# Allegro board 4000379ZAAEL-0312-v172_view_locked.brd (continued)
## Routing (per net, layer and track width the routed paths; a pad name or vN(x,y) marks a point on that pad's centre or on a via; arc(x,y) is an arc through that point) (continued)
PGND: length 56.5
  TOP w0.305: U909.23 v2(35.22,137.1) ; U909.18 v2(38.47,137.1) ; U909.11 38.47,134.04 v2(38.48,134.05) ; v2(35.88,134.05) 35.87,134.04 U909.7 ; U909.22 35.87,137.23 v2(36,137.1)
  TOP w0.381: 35.43,122.03 PU30.12 ; PU30.12 35.43,123 ; PU30.12 34.95,122.52 ; PU30.12 35.92,122.52 ; PU30.15 34.72,124.12 ; PU30.15 34.23,123.63 ; PU30.15 34.23,124.6 ; PU30.15 33.75,124.12 ; 36.15,122.52 PU30.10 ; PU30.10 37.12,122.52 ; PU30.10 36.63,122.03 ; PU30.10 36.63,123 ; 36.15,124.12 PU30.11 ; PU30.11 36.63,124.6 ; PU30.11 37.12,124.12 ; PU30.11 36.63,123.63 ; PU30.14 34.72,122.52 ; PU30.14 34.23,123 ; PU30.14 34.23,122.03 ; PU30.14 33.75,122.52 ; PU30.13 35.92,124.12 ; PU30.13 34.95,124.12 ; PU30.13 35.43,124.6 ; PU30.13 35.43,123.63
  TOP w0.508: U22.5 v2(22.61,135.38) ; C720.1 v2(26.42,133.48)
  L2 w0.381: 33.75,124.12 PU30.15 ; PU30.15 34.23,124.6 ; PU30.15 34.23,123.63 ; PU30.15 34.72,124.12 ; PU30.12 35.92,122.52 ; PU30.12 34.95,122.52 ; PU30.12 35.43,122.03 ; PU30.12 35.43,123 ; 36.15,122.52 PU30.10 ; PU30.10 37.12,122.52 ; PU30.10 36.63,123 ; PU30.10 36.63,122.03 ; PU30.13 35.92,124.12 ; PU30.13 35.43,124.6 ; PU30.13 34.95,124.12 ; PU30.13 35.43,123.63 ; PU30.11 36.63,124.6 ; PU30.11 37.12,124.12 ; PU30.11 36.63,123.63 ; PU30.11 36.15,124.12 ; PU30.14 34.23,123 ; PU30.14 34.72,122.52 ; PU30.14 33.75,122.52 ; PU30.14 34.23,122.03
  L3 w0.381: 36.63,123.63 PU30.11 ; PU30.11 36.15,124.12 ; PU30.11 37.12,124.12 ; PU30.11 36.63,124.6 ; PU30.10 36.63,123 ; PU30.10 37.12,122.52 ; PU30.10 36.63,122.03 ; PU30.10 36.15,122.52 ; PU30.12 35.92,122.52 ; PU30.12 35.43,123 ; PU30.12 35.43,122.03 ; PU30.12 34.95,122.52 ; PU30.15 34.23,124.6 ; PU30.15 33.75,124.12 ; PU30.15 34.72,124.12 ; PU30.15 34.23,123.63 ; PU30.13 35.92,124.12 ; PU30.13 35.43,123.63 ; PU30.13 35.43,124.6 ; PU30.13 34.95,124.12 ; 34.23,122.03 PU30.14 ; PU30.14 33.75,122.52 ; PU30.14 34.23,123 ; PU30.14 34.72,122.52
  BOTTOM w0.381: PU30.10 36.63,123 ; PU30.10 37.12,122.52 ; PU30.10 36.15,122.52 ; PU30.10 36.63,122.03 ; PU30.12 35.43,123 ; PU30.12 35.92,122.52 ; PU30.12 35.43,122.03 ; PU30.12 34.95,122.52 ; PU30.13 35.43,124.6 ; PU30.13 34.95,124.12 ; PU30.13 35.43,123.63 ; PU30.13 35.92,124.12 ; 36.63,123.63 PU30.11 ; PU30.11 37.12,124.12 ; PU30.11 36.15,124.12 ; PU30.11 36.63,124.6 ; PU30.14 34.23,123 ; PU30.14 33.75,122.52 ; PU30.14 34.72,122.52 ; PU30.14 34.23,122.03 ; PU30.15 34.72,124.12 ; PU30.15 34.23,124.6 ; PU30.15 33.75,124.12 ; PU30.15 34.23,123.63
  BOTTOM w0.508: C8572.1 v2(32.64,136.64)
  BOTTOM w0.762: v2(30.43,136.72) C8573.2
  vias: v2(6.35,105.03) v2(6.73,135.25) v2(6.73,131.32) v2(6.73,127.38) v2(6.73,123.06) v2(6.86,118.62) v2(7.75,114.55) v2(7.87,107.82) v2(8.89,137.79) v2(9.14,109.35) v2(9.14,108.58) v2(9.27,122.56) v2(9.53,133.22) v2(9.53,128.14) v2(9.65,116.46) v2(10.03,112.14) v2(10.03,110.62) v2(10.16,109.35) v2(10.16,108.58) v2(11.94,119.13) v2(12.06,137.79) v2(12.32,125.48) v2(13.02,109.35) v2(13.08,108.52) v2(13.84,136.14) v2(13.84,135.13) v2(13.97,109.35) v2(13.97,108.52) v2(14.35,122.43) v2(14.61,137.79) v2(15.11,136.21) v2(15.11,135.19) v2(16.51,136.21) v2(16.51,135.19) v2(16.89,125.35) v2(17.78,137.79) v2(17.97,136.21) v2(17.97,135.19) v2(19.68,122.56) v2(20.95,137.79) v2(22.35,119.89) v2(22.48,125.22) v2(22.61,131.44) v2(24.51,137.79) v2(25.02,117.35) v2(25.15,122.3) v2(25.4,128.4) v2(26.8,115.32) v2(28.07,137.79) v2(29.78,130.94) v2(30.48,134.3) v2(30.73,125.92) v2(30.8,138.75) v2(30.8,126.87) v2(31.05,115.57) v2(31.05,114.36) v2(31.69,126.87) v2(31.69,125.92) v2(31.69,124.97) v2(31.88,143.76) v2(32.26,115.57) v2(32.26,114.36) v2(32.64,126.87) v2(32.64,125.92) v2(32.64,124.97) v2(32.77,95) v2(32.77,91.19) v2(33.02,144.72) v2(33.15,107.7) v2(33.53,130.05) v2(33.46,115.57) v2(33.46,114.43) v2(34.04,99.82) v2(34.23,109.66) v2(34.23,108.65) v2(34.16,98.3) v2(34.92,130.05) v2(35.56,102.74) v2(36.07,129.29) v2(36.13,119.13) v2(36.2,117.47) v2(36.96,91.5) v2(37.59,101.35) v2(37.72,124.33) v2(37.72,122.87) v2(37.72,115.63) v2(37.72,114.49) v2(37.72,99.82) v2(37.72,98.42) v2(37.85,92.71) v2(38.93,144.78) v2(39.12,92.71) v2(39.37,140.46) v2(40.7,98.42) v2(40.7,96.84) v2(40.7,95.12) v2(40.7,93.54) v2(41.53,102.62) v2(41.66,140.46) v2(42.04,98.36) v2(42.04,96.77) v2(42.04,95.06) v2(42.04,93.47) v2(43.24,145.61) v2(43.24,144.78) v2(43.18,98.3) v2(43.18,96.71) v2(43.18,95) v2(43.18,93.41) v2(43.88,114.87) v2(44.01,125.03) v2(44.01,124.08) v2(44.01,123.06) v2(45.34,124.97) v2(46.61,124.97) v2(46.86,146.81) v2(46.86,145.03) v2(48.01,124.97) v2(49.09,114.94) v2(49.34,131.89) v2(49.34,124.21) v2(49.28,122.87) v2(49.4,135.89) v2(50.42,102.36) v2(51.05,139.7) v2(51.18,135.83) v2(51.18,131.89) v2(51.24,91.44) v2(51.56,145.8) v2(52.96,96.9) v2(53.09,117.41) v2(53.21,131.95) v2(55.12,107.95) v2(55.63,91.69) v2(55.69,123.63) v2(55.88,135.89) v2(57.09,122.24) v2(57.15,112.39) v2(57.28,103) v2(57.28,95.76)
SVDD0_CK: length 4.4
  TOP w0.203: v1(79.1,91.24) 79.1,91.27 79,91.36 E1U1.50
  BOTTOM w0.305: E1C97.1 79.62,91.24
  BOTTOM w0.508: v1(79.1,91.24) E1C98.1 81.53,91.24 E1C99.2 E1L5.2
SVDD0_TRX: length 0.8
  TOP w0.203: v1(77.5,91.19) 77.4,91.29 E1U1.46
VCC_0V6_DDR: length 29.3
  BOTTOM w0.203: R121.1 122.4,20.16 124.12,20.16 ; R123.1 122.39,25.52 124.12,25.52 ; 124.12,22.38 124.06,22.33 122.37,22.33 R128.1 ; R130.1 124.19,23.36 ; R125.1 124.12,24.48 122.38,24.48 R106.1
  BOTTOM w0.254: R119.1 116.89,30.94 116.89,33.23 117.42,33.23 R112.1 ; 124.73,21.24 122.25,21.24 R118.1 ; R107.1 120.3,28.2 122.29,28.2 R110.1 ; R113.1 120.43,29.28 122.29,29.28 R111.1 ; R109.1 124.12,25.52 ; 122.27,26.49 122.27,26.98 120.75,26.98 R105.1 ; R120.1 119.17,30.95 119.17,32.68 R116.1 118.49,32.8 118.02,32.8 118.02,30.86 R114.1
  vias: v2(127.76,23.55) v2(128.07,24.26) v2(128.07,22.83) v2(128.47,23.55)
VCC_0V9_PRX321: length 12.6
  TOP w0.127: R916.1 v2(125.96,60.79) 125.98,60.77
  TOP w0.203: U1.U14 v1(104.94,51.41) ; U1.P14 105.26,49.44 104.84,49.02
  TOP w0.254: U1.W22 102.04,51.88 v1(102.39,52.22) 102.73,51.88 U1.W20 ; U1.P18 v1(103.28,49.81) ; U1.W12 U1.U14 ; U1.T20 U1.T22 ; U1.P14 U1.T12
  TOP w0.305: v1(104.83,49.02) 104.88,49.02 U1.M14 ; 105.28,49.43 U1.P14 ; U1.T20 v1(103.19,50.6) 103.19,50.71 U1.U20 ; U1.P16 104.46,49.43 v1(104.07,49.04) 103.65,48.62 U1.M18 ; U1.U18 103.65,51.03 v1(104.01,50.67)
  BOTTOM w0.305: v1(102.39,52.22) 102.01,51.84 C209.1 C225.2 102.36,50.69 C215.1
  vias: v2(124.97,60.83) v2(124.97,59.94) v2(125.98,59.94)
VCC_0V9_PRX321_XFI: length 14
  TOP w0.203: U1.W10 106.89,51.88 v1(106.57,51.55) ; v1(100.86,53.01) 100.81,53.06 100.81,53.75 101.02,53.95 103.2,53.95 v1(103.3,53.85)
  TOP w0.254: U1.AC18 103.65,53.5 v1(103.3,53.85) ; v1(106.55,50.6) U1.T10 ; v1(100.86,53.01) 101.18,52.69 U1.AA24
  BOTTOM w0.305: v1(106.57,51.55) 106.32,51.31 106.04,51.31 C206.1 ; C189.1 98.91,53.08 C202.1 100.79,53.08 v1(100.86,53.01) ; v1(103.3,53.85) 103.75,53.4 104.52,53.4 105,52.93 105.35,52.93 C198.1 105.52,52.8 105.97,52.34 C206.1 ; C206.1 C2.1 105.98,50.6 v1(106.55,50.6)
VCC_1V0_8261BE: length 22.5
  TOP w0.203: E1U1.53 81.3,93.09 E1C58.2 ; v1(75.95,91.04) 75.8,91.18 E1U1.42 ; E1U1.32 71.51,93.49 70.99,92.97 70.99,91.69 E1C54.2 ; v1(80.9,94.8) 80.79,94.69 E1U1.57 ; 70.92,95.34 71.09,95.34 71.63,95.89 E1U1.26
  TOP w0.305: E1C54.2 70.11,91.62 E1C50.2 ; E1C51.2 70.92,96.1 E1C55.2 ; E1C37.2 82.02,93.01 E1C58.2 ; E1C56.2 v1(80.9,94.8)
  TOP w0.381: E1C50.2 E1C38.2 68.77,91.55 68.39,91.17 v1(68.39,90.81)
  TOP w0.508: v1(68.52,95.95) 68.52,96.44 E1C33.1 69.09,96.25 E1C30.1 70.77,96.25 E1C51.2 ; v1(83.92,92.92) E1C35.1 83.16,92.89 E1C37.2
  BOTTOM w0.305: E1C53.2 75.97,91.01 v1(75.95,91.04)
  BOTTOM w0.508: E1C36.1 81.56,95.99 E1C52.2 81.33,94.8 v1(80.9,94.8) ; E1C79.2 85.42,94.09 85.42,93.43 84.92,92.92 v1(83.92,92.92)
  vias: v1(68.26,89.41) v1(68.26,88.77) v1(68.26,88.07) v1(68.26,87.44) v1(68.83,89.41) v1(68.83,88.77) v1(68.83,88.07) v1(68.83,87.44) v1(71.12,102.43) v1(71.12,101.79) v1(71.75,102.43) v1(71.75,101.79) v1(74.61,87.94) v1(74.61,87.31) v1(83.24,89.03) v1(83.24,88.4) v1(83.85,89.01) v1(83.85,88.4)
VCC_1V8_PRX321: length 147.2
  TOP w0.254: v4(86.74,44.67) 87.15,44.67 91.13,48.65 91.13,48.84 R172.1
  TOP w0.305: C1004.1 120.21,60.91
  TOP w0.508: v4(86.74,44.67) v4(86.06,45.35) 86.06,45.36 C21.1 83.63,47.79 83.63,49.48 ; v4(104.39,60.77) 105.03,60.13 v1(105.03,58.01) ; v2(126.36,48.01) C1005.1 C1006.1 R984.1 128.3,48.75 PU902.5 ; 83.63,49.48 C16.1 ; 83.63,49.48 v4(83.63,51.51) ; PR113.1 143.87,34.39 v2(143.75,34.28) ; v2(120.21,56.07) v2(120.21,61.9) ; C18.1 v2(94.74,60.83)
  L3 w0.508: v2(143.75,34.28) 131.64,34.28 130.19,35.73 130.19,42.95 126.36,46.77 v2(126.36,48.01) ; v2(120.21,61.9) 120.02,61.72 111.56,61.72 109.98,60.13 105.03,60.13 v4(104.39,60.77) 104.33,60.83 v2(94.74,60.83) 94.17,60.26 92.38,60.26 v4(83.63,51.51)
  BOTTOM w0.127: 126.03,49.5 C926.1 ; C27.1 94.95,44.67 ; 119.23,55.85 C927.1 ; C26.1 93.45,44.67 ; C25.1 94.16,44.67 ; 117.35,51.89 C922.1
  BOTTOM w0.305: C22.1 124.65,51.94
  BOTTOM w0.508: 97.05,44.67 R928.1 ; 97.05,44.67 98.53,44.67 99.38,43.81 FB13.1 ; 97.05,44.67 v4(86.74,44.67) v4(86.06,45.35) ; FB10.1 104.33,57.5 104.84,58.01 v1(105.03,58.01) ; C23.1 114.28,54.42 114.28,54.48 113.78,54.99 112.72,54.99 FB15.1 ; C23.1 117.73,54.36 ; C23.1 FB6.1 ; 117.73,54.36 117.73,52.27 116.89,51.44 115.71,51.44 ; 117.73,54.36 119.44,56.07 v2(120.21,56.07) 123.51,56.07 124.65,54.93 124.65,50.89 126.36,49.17 v2(126.36,48.01) ; 115.71,51.44 115.71,51.83 115.87,51.99 FB5.1 ; 115.71,51.44 FB12.1
VCC_1V8_PRX321_PLL: length 24.6
  TOP w0.508: v2(125.86,53.09) 125.89,53.05 C1009.1 C1010.1 128.07,53.04 PU908.5
  BOTTOM w0.305: 114.87,57.08 C1012.1
  BOTTOM w0.508: FB14.1 108.81,56.48 109.39,57.07 R980.1 111,57.07 C20.1 C19.1 111.96,57.08 124.34,57.08 125.86,55.56 v2(125.86,53.09)
VCC_1V9_8261BE: length 15.7
  TOP w0.127: R939.1 85.03,77.83 85.15,77.96 85.9,77.96 v2(85.92,77.98)
  TOP w0.203: v1(71.5,92.39) 71.44,92.46 71.44,92.75 71.77,93.09 E1U1.33 ; E1U1.24 71.58,96.69 v1(71.5,96.77) ; E1U1.55 v1(79.35,93.89) ; E1U1.36 73.4,90.95 73.4,90.94 E1C74.2
  TOP w0.305: E1R25.1 E1R24.1 72.82,89.49 v1(72.86,89.44) 73.09,89.44 73.4,89.74 E1C75.2 E1C74.2
  TOP w0.381: E1R3.1 68.52,99.39 v1(68.52,98.81)
  BOTTOM w0.381: v1(68.52,98.81) 70.36,98.81 71.5,97.66 v1(71.5,96.77)
  BOTTOM w0.508: v1(79.35,93.89) 79.37,93.91 E1C69.2 80.11,93.88 E1C72.1
  vias: v1(82.17,103) v1(82.17,102.11) v1(82.93,103) v1(82.93,102.11) v2(85.92,79.95) v2(85.92,78.93) v2(86.93,79.95) v2(86.93,78.93) v2(86.93,78.04) v2(87.88,80.01) v2(87.88,78.93) v2(87.88,78.04) v2(91.57,103.25) v2(91.57,102.62) v2(91.57,101.85) v2(92.2,103.25) v2(92.2,102.62) v2(92.2,101.85) v2(92.84,103.25) v2(92.84,102.62) v2(92.84,101.85)
VCC_1V35_DDR: length 67.5
  TOP w0.152: v1(95.25,20.27) 95.35,20.37 96,20.37 96.41,20.78 96.57,20.79 U13.H2
  TOP w0.178: 96.56,17.59 96.37,17.59 95.96,17.18 95.29,17.18 v1(95.2,17.16) ; 96.56,17.59 U13.D2 ; 96.56,17.59 96.57,17.59
  TOP w0.203: U1.H25 100.27,47.13 100.27,47.39 100.01,47.65 100.01,47.96 100.28,48.23 100.79,48.23 v1(100.83,48.2) ; v1(107.31,47.41) U1.K8 107.75,47.84 107.75,48.59 U1.M8 ; U12.G7 112.94,19.99 113.04,19.89 113.36,19.89 113.87,19.38 v1(113.87,19.15) ; 117.74,15.19 U12.A1 ; 117.74,15.19 117.74,15.19 ; 117.74,15.19 117.74,15.38 117.13,15.99 116.94,15.99 U12.B2 ; 102.03,47.02 U1.H22
  TOP w0.254: U1.K24 101.21,47.81 v1(100.83,48.2) ; U13.A1 97.37,15.19 v1(97.77,14.79) ; U12.H2 116.94,20.79 v1(116.54,20.39) ; 90.96,24.79 90.97,24.79 ; 90.96,24.79 U13.N9 ; 90.96,24.79 89.71,24.79 89.41,25.12 v1(89.36,25.12) ; 111.33,26.39 111.34,26.39 ; 111.33,26.39 U12.R9 ; 111.33,26.39 111.22,26.39 v1(110.81,26.79) ; U12.N9 111.34,24.79 110.98,25.14 v1(110.76,25.14) ; v4(110.19,21.23) 110.6,20.82 111.31,20.82 111.34,20.79 U12.H9 ; v1(96.97,22.79) 96.57,22.39 U13.K2 ; v1(100.83,48.2) 100.83,48.24 ; v1(100.83,48.2) 101.21,48.58 U1.M24 ; v1(118.36,15.29) 118.29,15.21 118.29,15.19 117.74,15.19 ; v1(111.76,22.76) 111.77,22.76 112.14,22.39 U12.K8 ; v1(106.5,47.35) 106.5,47.4 106.09,47.81 U1.K12 ; v1(118.25,19.24) 118.14,19.19 117.74,19.19 U12.F1 ; U12.R1 117.74,26.39 118.01,26.11 v1(118.24,26.11) ; v1(98.18,26.78) 97.79,26.39 97.37,26.39 U13.R1 ; v1(97.8,25.22) 97.37,24.79 U13.N1 ; v1(118.41,16.87) 118.34,16.79 117.74,16.79 U12.C1 ; U1.H10 v1(107.31,47.41) ; U12.C9 111.34,16.79 v1(110.94,17.19) ; v1(117.34,17.99) 116.94,17.59 U12.D2 ; v1(90.32,16.87) 90.4,16.79 90.96,16.79 ; 90.96,16.79 90.97,16.79 ; 90.96,16.79 U13.C9 ; U12.K2 116.94,22.39 v1(117.33,22.79) ; U12.N1 117.74,24.79 v1(118.15,25.2) ; 107.72,47.81 U1.K8 ; U13.H9 90.97,20.79 v1(91.37,20.39) ; U13.C1 97.37,16.79 v1(96.97,16.39) 96.57,15.99 U13.B2 ; v1(92.14,22.77) 91.77,22.39 U13.K8 ; U13.G7 92.57,19.99 v1(92.97,19.59) ; U12.D9 111.34,17.59 v1(110.94,17.99) 111.34,18.39 U12.E9 ; v1(98.11,19.25) 97.39,19.25 97.37,19.19 U13.F1 ; U13.A8 91.77,15.19 v1(91.37,15.59) ; U1.H12 106.11,47 v1(106.5,46.61) ; v1(90.48,26.93) 90.48,26.88 90.97,26.39 U13.R9 ; v1(108.08,46.61) 108.47,47 U1.H6 ; U13.D9 90.97,17.59 v1(90.57,17.99) 90.97,18.39 U13.E9 ; v1(104.04,47.37) 104.06,47.39 104.06,47.41 U1.K16
  TOP w0.305: 101.62,46.61 101.62,46.6 ; 101.62,46.6 v1(101.61,46.58) ; 101.62,46.6 U1.H22 U1.K20 U1.H20 102.42,46.58 v1(102.41,46.58) 102.44,46.61 ; v1(112.19,14.5) 112.14,14.5 112.14,15.19 U12.A8 ; C116.1 v1(133.18,14.34)
  TOP w0.508: C973.1 104.01,11.81 v2(104.04,11.84) ; v2(131.29,22.35) 131.29,21.56 R938.1 ; C232.1 126.52,13.87 v2(127.09,14.44)
  BOTTOM w0.127: v1(106.5,46.61) 106.5,46.53 106.84,46.19 107.66,46.19 v1(108.08,46.61)
  BOTTOM w0.203: C102.1 110.38,27.06 110.43,27.01 110.62,26.79 v1(110.81,26.79) ; C115.1 89.44,27.77 90.27,26.93 v1(90.48,26.93)
  BOTTOM w0.254: C99.1 118.06,19.05 v1(118.25,19.24) ; C958.1 118.92,16.87 v1(118.41,16.87) ; 91.37,20.38 v1(91.37,20.39) ; v1(110.94,17.99) 111.19,18.24 111.19,18.49 C105.1 ; C104.1 118.65,25.19 118.17,25.19 v1(118.15,25.2) ; v1(91.37,15.59) 91.37,15.21 C961.1 ; C94.1 118.39,15.27 v1(118.36,15.29) ; v1(118.24,26.11) 118.36,25.99 C103.1 ; v1(112.19,14.5) 112.16,14.53 111.95,14.53 C960.1 ; v1(104.04,47.37) 103.57,47.37 C201.1 ; v1(110.94,17.19) 110.81,17.06 C95.1
  BOTTOM w0.305: v1(95.26,47.37) 95.26,46.96 C100.1 ; v4(110.19,21.23) 110.12,21.3 C96.1 ; C169.1 C168.1 100.82,48.2 v1(100.83,48.2) ; C142.1 117.31,18.01 v1(117.34,17.99) ; 102.41,46.57 v1(102.41,46.58) 102.06,46.24 C177.1 C191.1 ; v1(97.77,14.79) 97.89,14.91 C200.1 ; v1(90.57,17.99) 90.94,17.62 C112.1 ; v1(90.32,16.87) 90.37,16.81 C110.1 ; C113.1 97.83,25.25 v1(97.8,25.22) ; v1(95.25,20.27) 95.28,20.24 C959.1 ; C172.1 101.39,45.9 101.36,45.92 ; C195.1 98.21,19.15 v1(98.11,19.25) ; C140.1 92.74,19.28 92.97,19.51 v1(92.97,19.59) ; C159.1 98.25,26.71 v1(98.18,26.78) ; 101.36,45.92 C184.1 ; 101.36,45.92 101.36,46.34 v1(101.61,46.58) ; v1(91.37,20.39) 91.36,20.38 C106.1 ; C114.1 v1(111.58,38.84) ; C141.1 95.66,17.16 v1(95.2,17.16) ; v1(96.97,16.39) 97.14,16.56 C205.1
  BOTTOM w0.381: 102.41,46.58 v1(102.41,46.58)
  BOTTOM w0.457: C974.1 113.87,18.31 v1(113.87,19.15)
  BOTTOM w0.508: C971.1 102.22,19.6 v1(102.21,19.61) ; C972.1 94.25,17.31 v1(93.95,17.6)
  vias: v2(132.52,29.78) v2(132.52,28.77) v2(133.03,29.21) v2(133.79,29.21) v2(134.24,29.72) v2(134.24,28.64) v2(134.68,29.21)
VCC_3V3_8261BE: length 63.7
  TOP w0.203: 70.55,98.95 70.55,98.81 71.86,97.49 E1U1.22 ; E1U1.31 71.41,93.89 70.49,92.96 E1C91.1
  TOP w0.381: v1(69.47,92.2) 69.72,92.2 70.34,92.82 E1C91.1
  TOP w0.508: v2(85.28,86.04) 86.17,86.93 86.17,92.67 ER331.1 ; v1(69.18,98.2) 69.18,98.66 E1C88.1 70.42,99.08 70.55,98.95 E1C89.2 ; v2(67.37,91.69) 67.82,91.69 68.33,92.2 v1(69.47,92.2)
  TOP w1.016: RP1132.2 58.11,85.54 64.26,91.69 v2(67.37,91.69)
  L3 w0.508: v2(85.28,86.04) 76.9,86.04 76.14,85.28 v2(67.75,85.28)
  BOTTOM w0.508: v1(69.47,92.2) 69.58,92.31 E1C92.1 69.61,93.94 E1C90.2 69.61,97.78 v1(69.18,98.2)
  BOTTOM w1.016: v2(67.37,91.69) 67.37,86.42
VCC_3V3_PON: length 668.4
  TOP w0.203: v1(104.08,51.5) 104.04,51.46 101.61,51.46 U1.U24
  TOP w0.254: v1(100.84,51.41) 101.18,51.06 U1.U24 ; U1.AA25 100.66,52.43 v1(100.66,52.27) 100.66,52.14 U1.W25 ; U1.P6 108.43,49.44 108.15,49.16 108.15,48.96 v1(108.13,48.94) ; v1(104.08,51.5) 104.09,51.5 U1.W16
  TOP w0.305: 74.52,41.34 C277.1 ; C633.1 v2(45.47,16.38) ; C636.1 48.39,45.19 v2(49.01,45.19)
  TOP w0.508: D822.A 68.31,4.7 CE79.1 ; v2(26.67,144.46) 26.69,144.45 C719.1 ; U18.8 74.52,43.05 74.52,40.3 C278.1 v2(73.69,40.26) ; 99.12,58.89 v1(99.12,59.5) ; 99.12,58.89 R231.1 ; 99.12,58.89 99.16,58.85 R229.1 ; R833.1 45.48,14.62 v2(45.47,14.61) ; D823.A 68.57,3.3 CE78.1 CE79.1 ; R835.1 40.94,14.61 v2(40.26,14.61) ; PR610.2 v2(43.56,78.87) ; CE79.1 68.31,5.57 v2(68.33,5.59) ; PR464.2 54.63,73.33 54.61,73.34 ; CE81.1 CE80.1 78.35,3.3 D825.A ; CE81.1 D824.A ; CE81.1 78.15,5.51 v2(78.17,5.52) ; CE72.1 CE73.1 48.37,3.3 D810.A ; CE72.1 48.12,5.38 v2(48.13,5.4) ; CE72.1 D803.A ; PR462.2 v2(139.37,44.26) ; R155.1 v2(78.99,49.85) R181.1 ; R94.2 122.43,47.34 122.43,47.35 v2(122.43,47.75) 122.41,47.76 R93.2 v2(124.27,48.9) ; v2(88.27,4.76) 88.31,4.71 CE76.1 D805.A ; v2(134.91,48.04) 134.79,48.16 C1003.1 R977.1 133.76,48.75 PU902.1 ; 111.37,76.77 111.37,78.56 110.81,79.12 109.68,79.12 R235.1 ; 111.37,76.77 119.2,76.77 120.78,75.18 124.94,75.18 v2(124.97,75.16) ; 111.37,76.77 111.01,76.41 R234.1 v1(109.66,75.63) 109.09,75.06 102.04,75.06 100.46,76.64 v2(100.46,78.87) ; R839.1 67.58,14.68 v2(67.56,14.67) ; R233.1 v1(98.17,59.5) ; v2(123.24,51.97) 123.22,51.94 R185.1 R187.1 ; v2(96.47,83.39) 96.47,84.94 98.12,86.59 98.12,87.91 98.94,88.72 PR470.2 ; R956.1 v2(136.27,55.37) ; R837.1 57.67,14.67 v2(57.09,14.67) ; R958.1 v2(137.67,48.07) ; v2(35.12,14.61) 35.74,14.61 R830.1 ; v1(97.22,59.5) R183.1 ; R832.1 77.8,14.68 v2(77.79,14.67) ; D806.A 58.22,4.7 CE74.1 ; v2(58.23,5.59) 58.21,5.57 CE74.1 ; PR383.2 134.19,64.91 133.41,64.14 131.25,64.14 v2(130.49,63.37) ; v2(67.5,65.53) PR467.2 ; U22.1 26.42,142.88 26.69,143.14 C719.1 ; v2(22.42,143.7) R350.2 ; R230.1 v1(101.35,59.5) ; C719.1 R351.2 ; D802.A 98.28,4 CE75.1 98.3,4.02 v2(98.3,4.76) ; CE74.1 CE77.1 58.53,3.3 D804.A ; v2(62.1,14.67) 62.12,14.68 R838.1 ; R831.1 30.53,14.61 v2(29.84,14.61) ; R193.1 94.09,59.12 v1(93.66,59.12) 93.66,57.4 94.17,56.9 R152.1 ; R836.1 52.5,14.61 v2(51.82,14.61) ; v2(135.64,53.02) 135.61,53.05 C1008.1 R979.1 133.76,53.04 PU908.1 ; R834.1 72.66,14.68 v2(72.64,14.67) ; v1(106.24,65.6) 107.95,63.88 107.95,59.61 R232.1 R277.1 ; R258.1 v1(102.36,59.5) ; 51.88,83.31 52.01,83.44 51.82,83.63 51.82,86.61 52.32,87.12 57.34,87.12 62.42,92.2 62.42,140.08 49.23,153.27 v2(49.23,154.11) R809.2 ; R83.2 123.24,54.28 123.24,54.94 v2(123.19,54.99) 123.06,55.12 121.77,55.12 121.41,54.76 R89.2 R191.1
  L3 w0.508: v2(123.19,54.99) 123.24,54.94 v2(123.24,51.97) 123.24,49.92 v2(124.27,48.9) 125.29,47.88 125.29,45.85 v2(125.48,45.66) ; 106.24,65.59 v1(106.24,65.6) ; v2(57.09,14.67) 51.88,14.67 v2(51.82,14.61) v2(45.47,14.61) ; v2(57.09,14.67) 58.23,13.53 v2(58.23,5.59) ; v2(57.09,14.67) v2(62.1,14.67) v2(67.56,14.67) ; v2(43.56,78.87) 51.31,78.87 v2(52.13,79.69) ; v2(98.3,4.76) v2(88.27,4.76) 78.93,4.76 v2(78.17,5.52) 78.17,14.29 v2(77.79,14.67) v2(72.64,14.67) v2(67.56,14.67) ; v2(100.46,78.87) 99.89,79.44 99.89,81.42 97.92,83.39 v2(96.47,83.39) ; 45.47,19.88 v2(45.47,16.38) v2(45.47,14.61) ; v2(65.84,30.53) 66.24,30.53 73.69,37.97 v2(73.69,40.26) 80.7,40.26 83.62,43.18 83.62,50.09 ; v1(102.36,59.5) v1(101.35,59.5) v1(99.12,59.5) v1(98.17,59.5) v1(97.22,59.5) 96.84,59.12 v1(93.66,59.12) 92.61,59.12 v2(90.52,57.02) 90.52,56.99 83.62,50.09 ; v2(49.23,154.11) 47.51,154.11 40.65,147.26 29.46,147.26 v2(26.67,144.46) 25.91,143.7 v2(22.42,143.7) ; v2(67.56,14.67) 67.56,9.46 68.33,8.7 v2(68.33,5.59) ; v2(78.99,49.85) 83.38,49.85 83.62,50.09 ; v2(45.47,14.61) 45.47,11.62 48.13,8.95 v2(48.13,5.4) ; v2(45.47,14.61) v2(40.26,14.61) v2(35.12,14.61) v2(29.84,14.61) ; v2(135.64,53.02) 134.3,53.02 ; 137.67,48.02 v2(137.67,48.07) ; v2(67.5,65.53) 67.45,65.59 ; 134.25,55.37 v2(136.27,55.37)
  L3 w1.27: 124.93,65.59 67.45,65.59 67.44,65.6 v2(54.48,65.6) v2(53.4,65.6) ; v2(140.28,27.88) 144.78,27.88 146.81,29.91 146.81,41.78 144.65,43.94 139.69,43.94 v2(139.37,44.26) 139.37,46.32 137.65,48.04 v2(134.91,48.04) 134.3,48.64 134.3,53.02 134.25,53.08 134.25,55.94 130.49,59.69 v2(130.49,63.37) v2(128.94,64.93) 128.27,65.6 124.94,65.6
  L3 w1.524: 65.76,21.18 65.76,30.16
  BOTTOM w0.254: R203.1 114.37,48.81 114.11,49.07 109.96,49.07 109.28,48.39 C203.1 108.83,48.39 108.29,48.94 v1(108.13,48.94)
  BOTTOM w0.305: v1(100.66,52.27) 100.28,51.89 C199.1 C186.1 ; C186.1 100.66,51.23 v1(100.84,51.41) ; C186.1 99.31,50.94 99.11,50.75 98.2,50.75 97.76,51.18 C178.1 ; U604.8 46.04,24.06 C616.1 v4(46.04,22.5) ; v1(104.08,51.5) 104.05,51.52 103.62,51.52 C197.1 ; C192.1 93.98,54.42 ; C635.1 v4(44.1,27.31)
  BOTTOM w0.381: R630.2 47.38,24.16 U604.8
  BOTTOM w0.508: R203.1 R68.2 114.44,47.64 C173.1 116.66,47.64 117.08,48.06 122.12,48.06 v2(122.43,47.75) ; R629.2 47.62,27.94 46.55,29.02 46.55,30.16 ; v2(128.94,64.93) 127.7,63.69 127.7,59.63 127.06,58.99 113.24,58.99 R949.1 ; v2(62.1,14.67) 62.93,14.67 ; v2(90.52,57.02) 90.52,55.15 91.06,54.61 93.79,54.61 94.61,53.78 FB9.1 94.82,53.32 96.96,51.18 C178.1 ; v2(134.91,48.04) 133.79,46.93 128.78,46.93 127.51,45.66 v2(125.48,45.66)
  vias: v2(46.55,33.53) v2(46.55,32.77) v2(46.55,32.07) v2(47.37,33.53) v2(47.37,32.77) v2(47.37,32.07) v2(53.4,66.74) v2(54.48,66.74) v2(65.96,31.19) v2(66.62,31.22) v2(66.62,30.56) v2(124.41,72.77) v2(124.97,71.98) v2(125.53,72.77) v2(138.75,27.88) v2(139.4,28.57)
VCC_3V3_PRX321_GPHY: length 8.5
  TOP w0.254: 102.84,52.69 102.84,52.68 ; 102.84,52.69 102.65,52.88 102.23,52.88 102.03,52.68 ; 102.84,52.69 U1.AA20
  TOP w0.305: U1.AC24 101.22,53.49 101.54,53.17 ; 101.54,53.17 102.03,52.68 U1.AA22 ; 101.54,53.17 v1(101.54,53.16)
  BOTTOM w0.305: v1(101.54,53.16) 101.11,53.59 100.2,53.59 99.82,53.98 C182.2 C175.2 98.31,53.98 C166.2 C13.1 97.21,53.86 C170.2 95.75,53.86 FB9.2
VCC_3V3_PSE: length 26
  TOP w0.305: U909.24 34.57,136.8 v2(34.48,136.72) ; U909.1 v1(31.97,134.18)
  TOP w0.508: v2(27.21,135.6) 26.85,135.24 C720.2 U22.8 ; R353.2 25.15,133.86 v2(25.27,133.73) ; R352.2 23.88,133.86 v2(23.75,133.73)
  TOP w0.762: v2(29.34,132.65) 29.32,132.63 R495.2
  BOTTOM w0.508: v2(34.48,136.72) 34.54,136.65 D3.C 33.28,135.78 C8572.2 33.27,134.81 33.26,134.8 ; 33.26,134.8 32.48,134.8 31.97,134.29 v1(31.97,134.18) ; 33.26,134.8 R91.1
  BOTTOM w0.762: 29.34,135.76 33.26,135.76 C8572.2 ; 29.34,135.76 v2(29.34,132.65) ; 29.34,135.76 27.37,135.76 v2(27.21,135.6) 25.34,133.73 v2(25.27,133.73) v2(23.75,133.73)
VCC_20V0_SYS: length 90.8
  TOP w0.305: PU23.8 29.34,65.66 28.37,66.63 R1008.1
  TOP w0.508: v4(89.66,52.39) 83.31,52.39 v2(82.49,51.56) ; v2(72.52,51.56) 72.83,51.88 72.83,55.63 79.38,62.17 v2(79.44,62.17) ; R1008.1 v2(27.05,65.85)
  TOP w1.27: v2(15.81,143.45) v2(15.81,142.3)
  L3 w0.508: v2(21.53,65.47) 26.67,65.47 v2(27.05,65.85) ; v2(82.49,51.56) v2(72.52,51.56)
  L3 w1.27: v2(122.17,63.37) 81.92,63.37
  BOTTOM w0.508: v4(89.66,52.39) 93.22,52.39 96.41,49.2 R66.1
  vias: v2(16.89,143.45) v2(16.89,142.3) v2(17.91,143.45) v2(17.91,142.3) v2(18.41,73.28) v2(18.41,72.26) v2(18.41,71.25) v2(18.41,70.23) v2(18.92,143.45) v2(18.92,142.3) v2(19.56,73.28) v2(19.56,72.26) v2(19.56,71.25) v2(19.56,70.23) v2(57.4,62.42) v2(57.98,61.91) v2(58.55,62.42) v2(68.9,62.42) v2(69.47,61.91) v2(70.04,62.42) v2(80.01,62.8) v2(80.64,63.44) v2(91.82,74.55) v2(92.52,75.18) v2(93.09,75.76) v2(96.65,81.03) v2(96.65,80.14) v2(96.65,79.38) v2(122.75,63.69) v2(123.32,63.37) v2(127.7,56.64) v2(128.33,57.09) v2(128.33,56.2) v2(130.11,45.78) v2(130.68,45.28) v2(131.19,45.78)
VCC_20V0_USB_PD: length 23
  TOP w0.254: U27.13 32.13,153.1 v2(31.69,153.54) ; USB1.A4 33.59,162.13 33.85,161.87 v2(34.21,161.87) ; C8560.1 v2(23.3,159.38) ; USB1.B4 31.34,164.97 31.04,165.28 v2(30.89,165.28) ; v2(30.8,161.86) 31.09,162.16 USB1.A9 ; v2(34.16,165.35) 34.1,165.35 33.84,165.1 USB1.B9
  L3 w0.508: v2(34.21,161.87) 35.86,161.87 37.4,160.34 v2(37.4,155.38)
  BOTTOM w0.508: v2(31.69,153.54) 31.69,153.92 32.51,154.75 36.69,154.75 36.7,154.73 R999.1 36.89,154.73 37.4,155.24 v2(37.4,155.38)
  vias: v2(22.35,159.32) v2(24.26,159.32) v2(25.34,159.32)
VDD_DIG: length 6.8
  TOP w0.229: U601.4 62.49,34.8 v4(63.43,34.8)
  TOP w0.508: v4(63.56,30.93) 63.91,31.29 L607.2
  BOTTOM w0.127: C626.1 62.74,33.4
  BOTTOM w0.381: C625.1 62.74,32.91 62.74,34.18 C611.1 63.18,34.26 63.43,34.51 v4(63.43,34.8)
  BOTTOM w0.508: v4(63.56,30.93) 63.56,32.09 C625.1
VDD_RX: length 16.4
  TOP w0.102: C624.1 60.33,28.45
  TOP w0.203: 62.13,31.99 61.96,32.16 U601.32
  TOP w0.229: 62.13,31.99 C606.1
  TOP w0.508: v4(56.64,27.56) 57.15,28.07 59.15,28.07 59.53,28.45 61.52,28.45 62.28,29.21 R605.1 62.28,31.22 62.13,31.37 62.13,31.99
  BOTTOM w0.102: 51.36,29.13 L604.1
  BOTTOM w0.508: L604.1 54.48,29.13 55.67,27.94 56.26,27.94 v4(56.64,27.56)
VDD_TX: length 20.2
  TOP w0.127: U601.19 58.2,35.59 57.9,35.89 v4(57.69,35.89) ; U601.22 58.57,34.33 58.08,34.33 57.85,34.1 v4(57.7,34.1)
  TOP w0.508: v4(48.1,36.61) 48.08,36.62 v4(48.08,37.37) R610.1 ; R606.1 R604.1 R699.1 65.96,40.22 65.6,40.58 57.66,40.58 v4(57.47,40.39)
  L3 w0.508: v4(57.47,40.39) 57.53,40.32 57.53,38.86
  BOTTOM w0.305: C637.1 57.4,40.31 v4(57.47,40.39) ; C640.1 57.68,34.08 v4(57.7,34.1) ; C608.1 57.7,34.92
  BOTTOM w0.508: v4(57.69,35.89) 57.7,35.88 v4(57.7,34.1)
  vias: v4(49.02,36.99) v4(49.05,36) v4(49.85,36.99) v4(49.82,36)
1G_TCT_A: length 5.1
  TOP w0.508: 121.28,114.56 121.28,112.78 v2(121.22,112.71)
  BOTTOM w0.508: D69.2 121.22,113.68 v2(121.22,112.71) 121.22,111.87 C156.1
1G_TCT_B: length 5.1
  TOP w0.508: v2(125.09,112.78) T2.4
  BOTTOM w0.508: D72.2 125.09,113.36 v2(125.09,112.78) C276.1
1G_TCT_C: length 5.4
  TOP w0.508: T2.7 v2(128.91,112.71)
  BOTTOM w0.508: D70.2 128.91,112.98 v2(128.91,112.71) C139.1
1G_TCT_D: length 5.7
  TOP w0.508: v2(132.65,112.71) 132.72,112.78 T2.10
  BOTTOM w0.508: D71.2 134.57,114.63 v2(132.65,112.71) 132.65,111.87 C160.1
1GLAN_BIDA+: length 40.1
  TOP w0.279: P5.1 114.95,164.26 114.95,156.06 113.44,154.55 RV59.2 113.44,153.05 114.95,151.54 114.95,146.23 122.99,138.19 122.99,130.48 122.56,130.05 T2.23
1GLAN_BIDA-: length 38.4
  TOP w0.279: 123.83,129.02 123.83,130.05 123.39,130.48 123.39,138.35 115.35,146.39 115.35,151.51 116.69,152.84 RV59.1 116.69,154.75 115.36,156.08 115.36,161.87 P5.2
1GLAN_BIDB+: length 40.9
  TOP w0.279: P5.3 117.06,161.6 116.85,161.39 116.85,158.58 118.33,157.11 118.33,151.94 116.87,150.48 RV58.2 116.87,148.86 118.28,147.45 118.28,146.07 126.8,137.55 126.8,130.48 126.36,130.05 126.36,129.02
1GLAN_BIDB-: length 40.9
  TOP w0.279: T2.19 127.64,130.05 127.2,130.48 127.2,137.72 118.68,146.24 118.68,147.47 120.12,148.91 RV58.1 120.12,150.56 118.73,151.94 118.73,157.28 117.26,158.75 117.26,160.91 v2(117.51,161.16)
  BOTTOM w0.279: P5.6 118.73,161.16 v2(117.51,161.16)
1GLAN_BIDC+: length 39.9
  TOP w0.279: P5.4 118.69,161.94 118.69,159.86 121.68,156.87 121.68,156.06 120.42,154.8 RV57.2 120.42,153.05 121.81,151.66 121.81,146.22 130.61,137.42 130.61,130.48 130.18,130.05 T2.17
1GLAN_BIDC-: length 41.6
  TOP w0.279: P5.5 119.1,160.02 122.09,157.04 122.09,156.08 123.67,154.5 RV57.1 123.67,153.1 122.21,151.64 122.21,146.39 131.01,137.59 131.01,130.48 131.44,130.05 131.44,129.02
1GLAN_BIDD+: length 42.1
  TOP w0.279: T2.14 133.99,130.05 134.42,130.48 134.42,137.17 125.22,146.36 125.22,147.49 123.72,148.98 RV56.2 123.72,150.48 125.11,151.87 125.11,156.62 121.2,160.53 121.2,164.27 P5.7
1GLAN_BIDD-: length 40.5
  TOP w0.279: P5.8 121.6,161.99 121.6,160.7 125.52,156.78 125.52,151.89 126.97,150.43 RV56.1 126.97,148.91 125.63,147.56 125.63,146.53 134.82,137.34 134.82,130.48 135.25,130.05 T2.13
1GLAN_MCT_C: length 8.8
  TOP w0.762: T2.18 v2(128.91,130.94) C247.1
  BOTTOM w0.762: 128.91,128.96 v2(128.91,130.94) ; 128.91,128.96 D116.2 ; 128.91,128.96 D83.1
1GLAN_MCT_D: length 9.2
  TOP w0.762: C246.1 v2(132.72,130.94) T2.15
  BOTTOM w0.762: D85.1 D115.2 133.73,129.92 v2(132.72,130.94)
2G5_TCT_A0: length 6.7
  TOP w0.508: v2(91.5,112.39) 91.5,112.59 91.53,112.62 T17.1
  BOTTOM w0.508: D77.2 89.27,114.63 v2(91.5,112.39) 91.5,111.62 C280.1
2G5_TCT_A1: length 5.8
  TOP w0.508: T17.13 103.77,112.66 v2(103.76,112.65)
  BOTTOM w0.508: C284.1 v2(103.76,112.65) 103.76,113.35 105.04,114.63 D93.2
2G5_TCT_B0: length 6
  TOP w0.508: v2(94.55,112.65) 94.59,112.69 T17.4
  BOTTOM w0.508: C282.1 94.55,111.62 v2(94.55,112.65) 94.55,113.6 93.52,114.63 D88.2
2G5_TCT_B1: length 6.5
  TOP w0.508: v2(106.81,112.59) 106.83,112.61 T17.16
  BOTTOM w0.508: D96.2 108.85,114.63 v2(106.81,112.59) C286.1
2G5_TCT_C0: length 5.1
  TOP w0.508: T17.7 97.65,112.72 v2(97.66,112.71)
  BOTTOM w0.508: C279.1 v2(97.66,112.71) 97.66,113.99 D78.2
2G5_TCT_C1: length 7.7
  TOP w0.508: v2(109.92,112.39) 109.92,112.52 109.89,112.55 T17.19
  BOTTOM w0.508: C283.1 109.92,111.62 v2(109.92,112.39) 110.3,112.78 111.57,112.78 113.42,114.63 D94.2
2G5_TCT_D0: length 5.1
  TOP w0.508: v2(100.71,112.59) 100.71,112.59 T17.10
  BOTTOM w0.508: C281.1 v2(100.71,112.59) 100.71,114.12 D87.2
2G5_TCT_D1: length 8.9
  TOP w0.508: T17.22 v2(112.95,112.27)
  BOTTOM w0.508: C285.1 112.95,111.6 v2(112.95,112.27) 113.46,112.78 116.13,112.78 D95.2
2G5LAN_BIDA0+: length 43.6
  TOP w0.279: T17.47 92.55,130.15 92.84,130.43 92.84,131.32 91.8,132.36 91.8,138.9 90.64,140.06 86.64,140.06 81.65,145.05 81.65,151.54 80.16,153.02 RV63.2 80.16,154.57 81.65,156.06 81.65,164.26 P6.1
2G5LAN_BIDA0-: length 42
  TOP w0.279: T17.46 93.57,130.2 93.24,130.53 93.24,131.49 92.2,132.53 92.2,139.06 90.8,140.46 86.81,140.46 82.05,145.22 82.05,151.51 83.44,152.9 83.44,153.8 ; 83.44,153.8 83.44,154.7 82.05,156.08 82.05,161.87 P6.2 ; 83.44,153.8 RV63.1
2G5LAN_BIDA1+: length 39.4
  TOP w0.279: T17.35 104.79,130.19 105.1,130.5 105.1,139.5 98.3,146.31 98.3,151.54 96.8,153.03 RV67.2 96.8,154.56 98.3,156.06 98.3,164.26 P4.1
2G5LAN_BIDA1-: length 37.8
  TOP w0.279: P4.2 98.7,161.87 98.7,156.08 100.05,154.74 RV67.1 100.05,152.86 98.7,151.51 98.7,146.47 105.51,139.67 105.51,130.46 105.81,130.15 T17.34
2G5LAN_BIDB0+: length 44.7
  TOP w0.279: P6.3 83.76,161.6 83.55,161.39 83.55,158.58 85.03,157.11 85.03,151.94 83.59,150.51 RV62.2 83.59,148.83 84.98,147.45 84.98,144.7 87.59,142.09 92.67,142.09 95.92,138.84 95.92,130.46 95.61,130.16 T17.44
2G5LAN_BIDB0-: length 44.8
  TOP w0.279: v2(84.21,161.16) 83.96,160.91 83.96,158.75 85.43,157.28 85.43,151.94 86.84,150.53 RV62.1 86.84,148.93 85.38,147.47 85.38,144.87 87.76,142.49 92.84,142.49 96.33,139 96.33,130.5 96.63,130.19 T17.43
  BOTTOM w0.279: P6.6 85.43,161.16 v2(84.21,161.16)
2G5LAN_BIDB1+: length 39.9
  TOP w0.279: T17.32 107.85,130.21 108.16,130.51 108.16,139.74 101.63,146.28 101.63,147.45 100.23,148.84 RV65.2 100.23,150.5 101.68,151.94 101.68,157.11 100.2,158.58 100.2,161.39 100.41,161.6 P4.3
2G5LAN_BIDB1-: length 40
  TOP w0.279: T17.31 108.87,130.14 108.57,130.45 108.57,139.91 102.03,146.45 102.03,147.47 103.48,148.92 RV65.1 103.48,150.55 102.08,151.94 102.08,157.28 100.61,158.75 100.61,160.91 v2(100.86,161.16)
  BOTTOM w0.279: v2(100.86,161.16) 102.08,161.16 P4.6
2G5LAN_BIDC0+: length 42.9
  TOP w0.279: P6.4 85.39,161.94 85.39,159.86 88.38,156.87 88.38,156.06 87.02,154.7 RV61.2 87.02,153.15 88.51,151.66 88.51,145.46 90.2,143.76 94.17,143.76 98.98,138.95 98.98,130.94 98.67,130.63 T17.41
2G5LAN_BIDC0-: length 44.5
  TOP w0.279: 90.3,153.8 90.3,153.02 88.91,151.64 88.91,145.63 90.37,144.17 94.34,144.17 99.39,139.12 99.39,130.94 99.69,130.63 T17.40 ; 90.3,153.8 90.3,154.57 88.79,156.08 88.79,157.04 85.8,160.02 P6.5 ; 90.3,153.8 RV61.1
2G5LAN_BIDC1+: length 39.3
  TOP w0.279: P4.4 102.04,161.94 102.04,159.86 105.03,156.87 105.03,156.06 103.66,154.69 RV66.2 103.66,153.16 105.16,151.66 105.16,147.13 111.86,140.42 111.86,132.63 111.25,132.02 111.25,130.43 110.91,130.09 T17.29
2G5LAN_BIDC1-: length 40.8
  TOP w0.279: T17.28 111.93,130.13 111.66,130.4 111.66,131.85 112.27,132.46 112.27,140.59 105.56,147.29 105.56,151.64 106.91,152.98 RV66.1 106.91,154.61 105.44,156.08 105.44,157.04 102.45,160.02 P4.5
2G5LAN_BIDD0+: length 44
  TOP w0.279: P6.7 87.9,164.27 87.9,160.53 91.81,156.62 91.81,151.87 90.45,150.51 RV60.2 90.45,148.96 91.88,147.52 91.88,146.49 92.84,145.54 95.63,145.54 101.32,139.85 101.32,132.11 101.98,131.44 101.98,130.43 101.73,130.18 T17.38
2G5LAN_BIDD0-: length 42.5
  TOP w0.279: T17.37 102.75,130.16 102.39,130.53 102.39,131.61 101.73,132.27 101.73,140.02 95.8,145.95 93.01,145.95 92.29,146.66 92.29,147.52 93.7,148.93 RV60.1 93.7,150.41 92.21,151.89 92.21,156.78 88.3,160.7 88.3,161.99 P6.8
2G5LAN_BIDD1+: length 41.3
  TOP w0.279: P4.7 104.55,164.27 104.55,160.53 108.46,156.62 108.46,151.87 107.09,150.5 RV64.2 107.09,148.97 108.53,147.52 108.53,146.74 115.16,140.11 115.16,132.12 114.3,131.26 114.3,130.43 113.97,130.1 T17.26
2G5LAN_BIDD1-: length 39.8
  TOP w0.279: T17.25 114.99,130.12 114.71,130.4 114.71,131.09 115.57,131.95 115.57,140.27 108.94,146.9 108.94,147.52 110.36,148.95 110.36,149.73 ; RV64.1 110.36,149.73 ; 110.36,149.73 110.36,150.39 108.86,151.89 108.86,156.78 104.95,160.7 104.95,161.99 P4.8
2G5LAN_MCT_C0: length 16.3
  TOP w0.635: C256.1 97.66,130.95 v2(97.65,130.94) T17.42
  BOTTOM w0.762: v2(97.65,130.94) 91.01,130.94 D105.1 D124.2
2G5LAN_MCT_C1: length 16.7
  TOP w0.635: T17.30 109.89,132.76 C251.1
  TOP w0.762: C251.1 110.11,132.8 110.87,133.56 v2(110.87,138.94)
  BOTTOM w0.762: v2(110.87,138.94) 110.87,139.01 D101.1 D120.2
2G5LAN_MCT_D0: length 11.4
  TOP w0.635: C254.1 100.33,131.32 v2(100.71,130.94) T17.39
  BOTTOM w0.762: v2(100.71,130.94) 99.31,130.94 97.33,128.96 D123.2 D107.1
2G5LAN_MCT_D1: length 9.8
  TOP w0.635: T17.27 112.95,130.76 v2(112.9,130.81) 112.9,131.7 113.41,132.21 C250.1
  BOTTOM w0.762: v2(112.9,130.81) 112.9,128.96 ; 112.9,128.96 D103.1 ; 112.9,128.96 D119.2
10GLAN_BIDA+: length 39.5
  TOP w0.279: P3.1 65,164.26 65,156.06 63.53,154.58 RV55.2 63.53,153.01 65,151.54 65,145.63 71.73,138.9 71.73,130.4 71.37,130.05 T1.23
10GLAN_BIDA-: length 37.9
  TOP w0.279: P3.2 65.41,161.87 65.41,156.08 66.78,154.71 RV55.1 66.78,152.88 65.4,151.51 65.4,145.8 72.14,139.07 72.14,130.43 72.64,129.92 T1.22
10GLAN_BIDB+: length 40.4
  TOP w0.279: P3.3 67.11,161.6 66.9,161.39 66.9,158.58 68.38,157.11 68.38,151.94 66.95,150.52 RV54.2 66.95,148.82 68.33,147.45 68.33,146.81 75.62,139.52 75.62,130.48 75.18,130.05 T1.20
10GLAN_BIDB-: length 40.4
  TOP w0.279: T1.19 76.45,130.05 76.02,130.48 76.02,139.69 68.73,146.98 68.73,147.47 70.21,148.95 RV54.1 70.21,150.52 68.78,151.94 68.78,157.28 67.31,158.75 67.31,160.91 v2(67.56,161.16)
  BOTTOM w0.279: v2(67.56,161.16) 68.78,161.16 P3.6
10GLAN_BIDC+: length 39.5
  TOP w0.279: T1.17 78.99,130.05 79.38,130.43 79.38,139.32 71.86,146.84 71.86,151.66 70.38,153.14 RV53.2 70.38,154.71 71.73,156.06 71.73,156.87 68.74,159.86 68.74,161.94 P3.4
10GLAN_BIDC-: length 41
  TOP w0.279: T1.16 80.26,129.92 79.78,130.4 79.78,139.49 72.26,147.01 72.26,151.64 73.63,153.01 RV53.1 73.63,154.58 72.14,156.08 72.14,157.04 69.15,160.02 P3.5
10GLAN_BIDD+: length 41.5
  TOP w0.279: P3.7 71.25,164.27 71.25,160.53 75.16,156.62 75.16,151.87 73.81,150.52 RV52.2 73.81,148.95 75.23,147.52 75.23,146.89 83.16,138.96 83.16,130.4 82.8,130.05 T1.14
10GLAN_BIDD-: length 40.1
  TOP w0.279: T1.13 84.07,129.85 83.57,130.36 83.57,139.13 75.64,147.06 75.64,147.52 77.06,148.95 RV52.1 77.06,150.39 75.56,151.89 75.56,156.78 71.65,160.7 71.65,161.99 P3.8
10GLAN_MCT_C: length 12.7
  TOP w0.762: C243.1 v2(77.72,130.81) T1.18
  BOTTOM w0.762: D79.1 D112.2 74.62,130.81 v2(77.72,130.81)
10GLAN_MCT_D: length 9.1
  TOP w0.762: C242.1 v2(81.53,130.81) T1.15
  BOTTOM w0.762: D111.2 D81.1 81.53,129.59 v2(81.53,130.81)
10GPHY_MDI_BIDA_N: length 17
  TOP w0.091: v3(73.51,103.38) 73.37,103.24 73.37,99.82 E1U1.16 ; T1.3 72.64,113.66 72.18,113.2 72.18,111.56 v3(72.3,111.44) 72.23,111.37 72.23,110.46 72.3,110.38 RV42.1
  L3 w0.084: v3(72.3,111.44) 72.24,111.38 72.24,108.29 73.38,107.14 73.38,103.51 v3(73.51,103.38)
10GPHY_MDI_BIDA_P: length 17.1
  TOP w0.091: E1U1.17 73.03,99.81 73.03,103.25 v3(72.9,103.38) ; T1.2 71.37,113.66 71.84,113.2 71.84,111.59 v3(71.69,111.44) 71.88,111.25 71.88,110.49 71.81,110.41 RV42.2
  L3 w0.084: v3(72.9,103.38) 73.03,103.5 73.03,107 71.88,108.14 71.88,111.25 v3(71.69,111.44)
10GPHY_MDI_BIDB_N: length 19.9
  TOP w0.091: v3(75.34,103.33) 75.44,103.23 75.44,99.83 E1U1.11 ; RV41.1 76.24,110.38 76.2,110.43 76.2,111.34 v3(76.3,111.44) 76.15,111.6 76.15,112.45 75.95,112.66 75.95,113.22 76.45,113.73 T1.6
  L3 w0.084: v3(76.3,111.44) 76.17,111.57 76.17,111.9 75.88,112.19 74.98,112.19 74.32,111.53 74.32,108.56 75.44,107.45 75.44,103.43 v3(75.34,103.33)
10GPHY_MDI_BIDB_P: length 18.8
  TOP w0.091: v3(75.95,103.33) 75.91,103.33 75.78,103.2 75.78,99.81 E1U1.10 ; T1.5 75.18,113.66 75.6,113.25 75.6,112.51 75.8,112.31 75.8,111.55 v3(75.69,111.44) 75.85,111.28 75.85,110.53 75.74,110.41 RV41.2
  L3 w0.084: v3(75.95,103.33) 75.79,103.48 75.79,107.59 74.68,108.71 74.68,111.38 75.13,111.84 75.74,111.84 75.82,111.75 75.82,111.57 v3(75.69,111.44)
10GPHY_MDI_BIDC_N: length 17.6
  TOP w0.091: v3(77.9,104.27) 77.8,104.16 E1U1.5 ; RV40.1 80.18,110.23 80.18,111.27 v3(80.32,111.4) 80.14,111.58 80.14,112.44 79.8,112.77 79.8,113.27 80.26,113.73 T1.9
  L3 w0.084: v3(80.32,111.4) 80.17,111.26 80.17,109.7 77.79,107.31 77.79,104.38 v3(77.9,104.27)
10GPHY_MDI_BIDC_P: length 17.6
  TOP w0.091: T1.8 78.99,113.73 79.46,113.27 79.46,112.63 79.79,112.3 79.79,111.49 v3(79.71,111.4) 79.83,111.28 79.83,110.25 RV40.2 ; v3(77.29,104.27) 77.45,104.1 77.45,99.84 E1U1.6
  L3 w0.084: v3(77.29,104.27) 77.43,104.41 77.43,107.46 79.81,109.84 79.81,111.3 v3(79.71,111.4)
10GPHY_MDI_BIDD_N: length 21.8
  TOP w0.091: E1U1.3 78.65,99.84 78.65,100.18 78.59,100.25 78.59,101.95 79.47,102.84 79.47,104.22 v3(79.35,104.34) ; T1.12 84.07,113.66 83.61,113.2 83.61,112.84 84.37,112.08 84.37,111.54 v3(84.51,111.4) 84.36,111.25 84.36,110.24 RV39.1
  L3 w0.084: v3(79.35,104.34) 79.46,104.46 79.46,106.71 82.23,109.47 82.23,111.7 82.88,112.34 84,112.34 84.38,111.96 84.38,111.53 v3(84.51,111.4)
10GPHY_MDI_BIDD_P: length 20.6
  TOP w0.091: RV39.2 84.01,110.24 84.01,111.29 v3(83.9,111.4) 84.02,111.53 84.02,111.94 83.27,112.69 83.27,113.2 82.8,113.66 T1.11 ; v3(79.96,104.34) 79.82,104.2 79.82,102.7 78.93,101.81 78.93,100.39 79,100.32 E1U1.2
  L3 w0.084: v3(79.96,104.34) 79.82,104.48 79.82,106.56 82.59,109.33 82.59,111.55 83.03,111.99 83.85,111.99 84.02,111.82 84.02,111.53 v3(83.9,111.4)
10GPHY_TCT_A: length 54.2
  TOP w0.127: E1C150.1 81.53,111.76 ; E1C151.1 78.15,111.76 ; E1C149.1 70.1,111.89 ; C136.1 70.1,111 ; E1C152.1 74.15,111.76
  TOP w0.508: v2(83.69,107.7) 81.52,107.7 ; 81.52,107.7 81.52,110.83 C137.1 81.53,110.92 v2(81.53,112.9) T1.10 ; 81.52,107.7 78.15,107.7 ; 74.16,107.7 74.15,107.7 C148.1 74.15,112.66 v2(73.91,112.9) T1.4 ; 74.16,107.7 78.15,107.7 ; 74.16,107.7 70.8,107.7 70.09,108.41 E1C14.1 70.09,110.05 70.1,110.06 v2(70.1,112.9) T1.1 ; T1.7 v2(77.72,112.9) 77.72,112.65 78.15,112.22 C151.1 78.15,107.7
  BOTTOM w0.508: v2(73.91,112.9) 73.91,114.25 D66.2 ; v2(77.72,112.9) 77.72,113.98 78.37,114.63 D67.2 ; v2(83.69,107.7) 83.69,108.91 84.2,109.42 E1C16.1 85.66,109.73 E1L1.2 ; v2(81.53,112.9) 81.53,113.49 D68.2 ; D65.2 v2(70.1,112.9)
APD_BIAS: length 2.4
  TOP w0.381: v4(54.74,26.67) 54.87,26.8 U602.2
  BOTTOM w0.508: R662.2 55.43,26.6 ; 55.43,26.6 55.42,26.59 54.82,26.59 v4(54.74,26.67) ; 55.43,26.6 C612.2
APD_FB: length 3.5
  TOP w0.229: v4(62.9,36.89) 62.9,36.62 62.67,36.39 U601.8
  BOTTOM w0.381: R651.2 R648.2 61.96,36.46 62.28,36.78 R664.1 62.67,37.12 v4(62.9,36.89)
APD_PWM: length 18.9
  TOP w0.127: R617.1 v1(65.41,36.32)
  BOTTOM w0.127: Q600.G 60.31,22.1 63.17,22.1 64.5,23.43 R647.1 64.5,26.88 64.76,27.14 64.76,31.49 65.15,31.88 65.15,31.88 65.41,32.13 v1(65.41,36.32)
BS_CLK_SEL: length 2.6
  TOP w0.102: E1R26.2 81.79,91.47 80.57,92.69 E1U1.52
BS_MDI_ORDER: length 2.3
  TOP w0.102: E1U1.35 72.62,91.99 71.99,91.35 71.99,90.56 72.01,90.54 E1R24.2
BS_PHY_DIS: length 3
  TOP w0.102: E1U1.34 72.05,92.69 71.95,92.59 71.95,92.2 71.37,91.63 71.37,90.66 E1R25.2
BS_PHYAD0: length 5.1
  TOP w0.127: E1R27.1 73.79,88.01 74.83,89.05 74.83,90.99 75.4,91.56 E1U1.41
BS_PHYAD1: length 5.3
  TOP w0.127: E1R28.1 74.57,89.29 74.57,91.17 75,91.59 E1U1.40
BS_PHYAD2: length 5.9
  TOP w0.127: E1R29.1 72.41,88.07 72.96,88.07 74.32,89.43 74.32,91.29 74.6,91.57 E1U1.39
BS_PHYAD3: length 6.5
  TOP w0.102: E1R30.1 71.71,88.33 72.83,88.33 74.07,89.56 74.07,91.47 74.2,91.6 E1U1.38
BS_PHYAD4: length 7
  TOP w0.102: E1U1.37 73.8,89.67 72.71,88.58 71.01,88.58 E1R31.1
CC1: length 10.7
  TOP w0.127: v1(32.93,162.04) 33.09,162.2 USB1.A5 ; D128.2 28.96,158.81 ; 28.96,158.81 29.21,158.56 29.21,158.04 R1039.2 ; 28.96,158.81 29.21,159.07 29.21,159.32 v1(28.96,159.58)
  L3 w0.127: v1(28.96,159.58) 29.21,159.32 29.21,158.88 29.59,158.5 31.14,158.5 32.46,159.82 32.46,161.89 32.61,162.04 v1(32.93,162.04)
CC2: length 11.2
  TOP w0.127: v1(29.65,159.58) 29.46,159.38 29.46,159 29.65,158.81 ; D127.2 29.65,158.81 ; 29.65,158.81 29.46,158.62 29.46,158.1 R1040.2 ; v1(31.78,163.7) 31.84,163.77 USB1.B5
  L3 w0.127: v1(31.78,163.7) 32.21,163.27 32.21,159.94 31.01,158.75 29.72,158.75 29.46,159 29.46,159.38 v1(29.65,159.58)
CLK_XTALI_50MHZ_RTL8261BE: length 2.6
  TOP w0.127: E1R1.1 83.28,98.61 EC300.2 83.85,98.66 84.62,99.44 EY300.3
CLK_XTALO_50MHZ_RTL8261BE: length 4.7
  TOP w0.127: E1R2.1 83.29,97.74 EC301.2 83.39,97.79 83.79,98.2 85.62,98.2 86.47,97.35 EY300.1
COMP: length 20
  TOP w0.305: U39.4 v2(35.43,85.2) ; PU23.3 29.34,70.36 v2(29.21,70.48)
  L3 w0.305: v2(29.21,70.48) 33.27,74.54 33.27,83.04 v2(35.43,85.2)
CS+: length 5
  TOP w0.254: U27.7 35.43,155.63 35.56,155.77 35.56,155.89
  TOP w0.508: R992.2 39.21,156.86 C8558.1 36.53,156.86 35.56,155.89
D+: length 11
  TOP w0.127: R357.2 34.86,158.48 34.86,159.05 D110.2 34.86,159.98 34.86,160.39 34.52,160.73 32.77,160.73 32.45,161.05 32.45,162.37 32.59,162.52 USB1.A6 32.59,163.35 32.89,163.65 v1(33.05,163.65) ; USB1.B6 32.34,164.91 32.61,165.18 v1(32.79,165.18)
  L3 w0.127: v1(32.79,165.18) 32.79,163.91 v1(33.05,163.65)
D-: length 9.2
  TOP w0.127: R358.2 34.54,158.48 34.54,159.05 D109.2 34.61,160.04 34.61,160.26 34.39,160.48 32.64,160.48 32.19,160.92 32.19,162.37 32.09,162.47 USB1.A7 32.09,163.36 32.84,164.11 USB1.B7
DDR_A0: length 87.8
  TOP w0.102: U12.N3 116.14,24.79 116.03,24.89 116.03,24.94 115.69,25.28 v1(115.69,26.01) ; 95.76,24.79 95.77,24.79 ; 95.76,24.79 95.32,25.24 v1(95.32,26.02) ; 95.76,24.79 U13.N3 ; v1(101.04,35.75) 101.03,35.76 100.89,35.76 100.82,35.84 100.82,39.58 101.04,39.8 101.04,39.93 100.77,40.2 100.77,40.6 101.04,40.87 101.04,41 100.82,41.22 100.82,41.63 100.97,41.78 100.97,41.94 100.82,42.09 100.82,42.52 101.1,42.81 101.1,43.75 101.03,43.82 101.03,44.16 101.22,44.34 101.22,44.82 U1.C23
  BOTTOM w0.102: R105.2 119.74,25.89 119.51,25.65 117.78,25.65 117.73,25.6 117.08,25.6 116.83,25.35 116.32,25.35 115.69,25.98 v1(115.69,26.01) 115.69,26.02 115.39,26.02 114.09,27.32 112.37,27.32 111.18,28.5 109.3,28.5 108.39,27.58 104.27,27.58 104.19,27.51 104.19,26.72 104.11,26.64 103.86,26.64 103.78,26.72 103.78,26.85 103.73,26.9 103.45,26.9 103.38,26.82 103.38,26.72 103.3,26.64 102.21,26.64 101.45,25.88 97.54,25.88 97.27,25.62 96.79,25.62 96.5,25.33 95.96,25.33 95.44,25.85 95.44,25.99 95.41,26.02 v1(95.32,26.02) 94.96,26.02 93.67,27.3 91.85,27.3 91.36,27.79 91.36,27.96 90.22,29.1 90.22,31.88 90.3,31.95 93.34,31.95 93.42,32.03 93.42,34.24 93.5,34.32 94.34,34.32 94.41,34.39 94.41,35.23 94.49,35.31 94.79,35.31 94.87,35.23 94.87,34.39 94.95,34.32 95.17,34.32 95.25,34.39 95.25,36.22 95.33,36.3 95.63,36.3 95.71,36.22 95.71,34.39 95.78,34.32 96.04,34.32 96.11,34.39 96.11,36.22 96.19,36.3 96.44,36.3 96.52,36.22 96.52,34.39 96.6,34.32 96.85,34.32 96.93,34.39 96.93,36.22 97,36.3 97.26,36.3 97.33,36.22 97.33,34.39 97.41,34.32 97.66,34.32 97.74,34.39 97.74,36.22 97.82,36.3 98.07,36.3 98.15,36.22 98.15,34.39 98.22,34.32 98.83,34.32 98.91,34.39 98.91,34.59 98.83,34.67 98.63,34.67 98.55,34.75 98.55,34.9 98.63,34.98 98.83,34.98 98.91,35.05 98.91,35.2 98.83,35.28 98.63,35.28 98.55,35.36 98.55,36.22 98.63,36.3 98.88,36.3 98.96,36.22 98.96,35.69 99.03,35.61 99.29,35.61 99.36,35.69 99.36,36.22 99.44,36.3 99.69,36.3 99.77,36.22 99.77,35.69 99.85,35.61 100.13,35.61 100.2,35.69 100.2,36.2 100.3,36.3 100.51,36.3 100.58,36.22 100.58,35.69 100.71,35.56 100.94,35.56 101.04,35.66 v1(101.04,35.75)
DDR_A1: length 91.9
  TOP w0.102: v1(101.88,37.67) 101.89,37.68 101.89,38.49 101.77,38.62 101.77,38.76 101.89,38.89 101.89,39.28 101.63,39.55 101.63,39.67 101.89,39.94 101.89,44.36 101.76,44.49 U1.B22 ; v1(113.49,26.08) 112.96,25.59 112.94,25.59 U12.P7 ; v1(93.09,26.09) 92.59,25.58 U13.P7
  BOTTOM w0.102: 113.37,26 110.68,26 110.16,26.52 108.96,26.52 108.9,26.47 107.72,26.47 107.65,26.39 107.65,26.16 107.72,26.09 108.09,26.09 108.17,26 108.17,25.82 108.07,25.73 107.72,25.73 107.65,25.66 107.65,25.37 107.59,25.32 102.69,25.32 101.55,24.18 101.07,24.18 100.99,24.1 100.99,23.72 100.91,23.65 100.51,23.65 100.43,23.72 100.43,24.1 100.36,24.18 96.91,24.18 96.53,23.8 95.88,23.8 95.53,24.16 95.1,24.16 94.77,24.48 94.77,24.77 93.45,26.09 v1(93.09,26.09) 92.93,25.92 92.57,25.92 92.43,26.06 92.15,26.06 91.87,25.78 90.74,25.78 88.77,27.75 88.77,29.82 88.7,29.9 86.33,29.9 86.26,29.97 86.26,30.23 86.33,30.3 88.65,30.3 88.7,30.35 88.7,30.66 88.65,30.71 86.33,30.71 86.26,30.78 86.26,31.06 86.31,31.11 88.65,31.11 88.7,31.17 88.7,31.47 88.65,31.52 86.33,31.52 86.26,31.6 86.26,31.88 86.31,31.93 88.65,31.93 88.7,31.98 88.7,32.28 88.65,32.33 86.31,32.33 86.26,32.38 86.26,32.69 86.31,32.74 87.17,32.74 87.25,32.82 87.25,33.07 87.17,33.15 86.33,33.15 86.26,33.22 86.26,35.65 88.43,37.82 101.12,37.82 101.37,37.57 101.78,37.57 v1(101.88,37.67) ; 113.37,26 113.48,26.07 113.83,26.07 115.1,24.79 115.1,24.51 115.47,24.14 115.9,24.14 116.32,23.72 116.71,23.72 116.96,23.98 120.65,23.98 121.07,24.4 R106.2 ; 113.37,26 v1(113.49,26.08)
DDR_A2: length 86.9
  TOP w0.102: U13.P3 95.77,25.59 v1(96.18,26) ; U12.P3 116.14,25.59 v1(116.55,26) ; v1(104.34,35.51) 104.34,34.92 104.42,34.85 105.84,34.85 105.92,34.77 105.92,34.52 105.84,34.44 103.84,34.44 103.76,34.37 103.76,32.66 103.66,32.56 102.64,32.56 102.51,32.69 102.51,33.78 102.59,33.86 102.98,33.86 103.02,33.9 103.02,34.28 102.94,34.37 102.59,34.37 102.51,34.44 102.51,35.15 102.59,35.23 102.87,35.23 103.23,35.59 103.23,35.88 103.16,35.95 102.49,35.95 102.41,35.88 102.41,35.69 102.34,35.61 102.08,35.61 102.01,35.53 102.01,35.2 101.93,35.13 101.57,35.13 101.5,35.2 101.5,35.92 101.57,35.99 101.88,35.99 101.96,36.07 101.96,36.32 101.88,36.4 101.27,36.4 101.19,36.47 101.19,36.73 101.27,36.8 102.18,36.8 102.26,36.88 102.26,37.13 102.18,37.21 101.22,37.21 101.14,37.29 101.14,38.06 101.21,38.13 101.52,38.13 101.6,38.2 101.6,38.43 101.52,38.51 101.22,38.51 101.14,38.58 101.14,38.81 101.19,38.86 101.52,38.86 101.6,38.94 101.6,39.17 101.52,39.24 101.22,39.24 101.14,39.32 101.14,39.55 101.66,40.07 101.66,44.16 101.45,44.37 101.45,44.61 101.76,44.92 101.76,45.33 U1.D22
  BOTTOM w0.102: R107.2 119.25,28 119.25,27.73 118.3,26.79 117.34,26.79 v1(116.55,26) 116.54,26.02 116.54,26.19 115.91,26.82 115.31,26.82 114.4,27.72 112.55,27.72 111.37,28.9 109.1,28.9 108.19,27.99 102.23,27.99 102.16,27.91 102.16,27.23 102.08,27.15 101.88,27.15 101.8,27.23 101.8,27.91 101.73,27.99 101.47,27.99 101.4,27.91 101.4,26.49 101.22,26.31 97.64,26.31 97.31,26.64 96.57,26.64 96.44,26.51 96.44,26.26 v1(96.18,26) 96.14,26.03 96.14,26.14 95.63,26.66 94.89,26.66 93.84,27.71 92.08,27.71 91.77,28.02 91.77,28.14 90.84,29.08 90.84,31.27 90.91,31.34 93.95,31.34 94.03,31.42 94.03,33.6 94.11,33.68 99.44,33.68 99.52,33.76 99.52,34.92 99.59,35 102.11,35 102.18,35.08 102.18,35.59 102.26,35.66 104.17,35.66 v1(104.34,35.51)
DDR_A3: length 88.2
  TOP w0.102: v1(96.98,25.2) 96.57,24.79 U13.N2 ; U1.A21 102.19,44.09 102.19,43.99 102.12,43.92 102.12,38.4 102.58,37.94 102.58,36.62 v1(102.81,36.4) ; v1(117.34,25.19) 116.94,24.79 U12.N2
  BOTTOM w0.102: R108.2 121.44,26.31 120.73,26.31 120.66,26.23 120.66,25.55 119.9,24.79 117.73,24.79 v1(117.34,25.19) 117.28,25.13 116.24,25.13 115.79,25.59 115.53,25.59 114.01,27.11 112.28,27.11 111.1,28.29 109.41,28.29 108.49,27.38 105.71,27.38 105.56,27.23 105.34,27.23 105.18,27.38 104.93,27.38 104.85,27.3 104.85,27.13 104.78,27.05 104.57,27.05 104.5,26.97 104.5,26.77 104.57,26.7 104.78,26.7 104.85,26.62 104.85,26.42 104.78,26.34 102.31,26.34 100.99,25.02 100.81,25.02 100.74,25.1 100.74,25.55 100.66,25.63 100.41,25.63 100.33,25.55 100.33,25.1 100.25,25.02 100,25.02 99.92,25.1 99.92,25.55 99.8,25.68 97.66,25.68 97.17,25.19 97,25.19 96.99,25.2 v1(96.98,25.2) 96.88,25.1 95.89,25.1 95.46,25.53 95.16,25.53 93.59,27.1 91.74,27.1 91.16,27.69 91.16,27.88 89.92,29.12 89.92,32.18 89.99,32.26 91.82,32.26 91.9,32.33 91.9,36.55 91.97,36.63 92.28,36.63 92.35,36.55 92.35,32.31 92.43,32.23 93.07,32.23 93.14,32.31 93.14,32.66 93.07,32.74 92.81,32.74 92.74,32.82 92.74,33.17 92.81,33.25 93.07,33.25 93.14,33.32 93.14,33.58 93.07,33.66 92.81,33.66 92.74,33.73 92.74,33.99 92.81,34.06 93.07,34.06 93.14,34.14 93.14,34.39 93.07,34.47 92.81,34.47 92.74,34.54 92.74,34.8 92.81,34.87 93.22,34.87 93.29,34.95 93.29,35.2 93.22,35.28 92.81,35.28 92.74,35.36 92.74,35.61 92.81,35.69 93.22,35.69 93.29,35.76 93.29,36.12 93.22,36.2 92.81,36.2 92.74,36.27 92.74,36.55 92.81,36.63 93.6,36.63 93.68,36.55 93.68,34.65 93.75,34.57 94.01,34.57 94.08,34.65 94.08,36.55 94.16,36.63 94.41,36.63 94.49,36.55 94.49,35.69 94.56,35.61 94.82,35.61 94.89,35.69 94.89,36.53 94.97,36.6 100.69,36.6 101,36.3 102.67,36.3 102.77,36.4 v1(102.81,36.4)
DDR_A4: length 95.8
  TOP w0.102: v1(111.73,26.82) 111.73,25.99 112.14,25.59 U12.P8 ; 91.76,25.59 91.37,25.99 91.37,26.68 91.32,26.73 91.31,26.73 v1(91.37,26.79) ; 91.76,25.59 U13.P8 ; 91.76,25.59 91.77,25.59 ; v1(103.1,37.06) 103.2,37.16 103.23,37.16 103.23,37.75 102.35,38.62 102.35,43.74 102.41,43.8 102.41,44.25 102.19,44.47 102.19,44.92 U1.C21
  BOTTOM w0.102: v1(103.1,37.06) 103.1,37.13 102.9,37.13 102.36,36.6 101.12,36.6 100.82,36.91 88.85,36.91 88.77,36.83 88.77,36.22 88.85,36.14 89.23,36.14 89.31,36.22 89.31,36.42 89.38,36.5 91.52,36.5 91.59,36.42 91.59,36.17 91.52,36.09 89.79,36.09 89.71,36.02 89.71,35.76 89.79,35.69 91.52,35.69 91.59,35.61 91.59,35.36 91.52,35.28 89.76,35.28 89.69,35.2 89.69,34.95 89.76,34.87 91.52,34.87 91.59,34.8 91.59,34.54 91.52,34.47 89.31,34.47 89.23,34.39 89.23,34.16 89.31,34.09 91.52,34.09 91.59,34.01 91.59,33.71 91.52,33.63 89.31,33.63 89.23,33.55 89.23,33.32 89.31,33.25 91.52,33.25 91.59,33.17 91.59,32.72 91.52,32.64 89.69,32.64 89.61,32.56 89.61,29.14 90.96,27.79 90.96,27.38 91.37,26.97 v1(91.37,26.79) 91.48,26.9 93.5,26.9 95.1,25.3 95.4,25.3 95.86,24.85 96.52,24.85 96.58,24.79 101.12,24.79 102.41,26.09 105.03,26.09 105.11,26.16 105.11,26.87 105.18,26.95 105.38,26.95 105.59,26.75 105.84,26.75 105.92,26.82 105.92,27.1 105.99,27.18 108.59,27.18 109.51,28.09 111.02,28.09 111.51,27.6 111.51,27.05 v1(111.73,26.82) 111.82,26.91 113.92,26.91 115.47,25.36 115.71,25.36 116.15,24.92 116.99,24.92 117.32,24.59 119.99,24.59 120.91,25.51 120.91,25.74 121.15,25.98 123.24,25.98 R109.2
